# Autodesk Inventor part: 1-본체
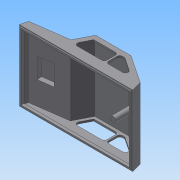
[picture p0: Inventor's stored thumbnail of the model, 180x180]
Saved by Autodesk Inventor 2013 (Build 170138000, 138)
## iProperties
Created: 2015-06
Part Number: 1-본체
Material: 일반
Document SubType Name: Modeling
Designer: Administrator
Density: 1 g/cm^3
Author: Administrator
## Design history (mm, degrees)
sketch "스케치1"
  geometry: L1 (0, 0)-(-122, 0); L2 (-122, 0)-(-119.856, 8); L3 (-119.856, 8)-(-80, 13.463); L4 (-80, 13.463)-(-70.99, 31); L5 (-70.99, 31)-(-32.947, 31); L6 (-32.947, 31)-(-2.947, 11); L7 (-2.947, 11)-(0, 0)
  constraints: 14 end point, 1 horizontal, 1 parallel
  dimensions: "d0" = 122 distance of L1.start L1.end; "d1" = 8 vertical distance of L1.end L2.end; "d2" = 42 horizontal distance of L3.end L1.end; "d6" = 105 deg angle of L1 L2; "d7" = 125 deg angle of L4 L3; "d8" = 20 vertical distance of L6.end L5.end; "d9" = 105 deg angle of L1 L7; "d10" = 31 vertical distance of L5.end L1.start; "d11" = 30 horizontal distance of L5.end L6.end; "d12" = 42.1946 deg angle of L4 L7
extrude "돌출1" new body sketch "스케치1" stored distance "d13" = 76; taper "d14" = 0 deg
sketch "스케치2"
  geometry: L1 (122, -76)-(122, 0) reference; L2 (0, 0)-(122, 0) reference; L3 (0, 0)-(0, -76) reference; L4 (122, -76)-(0, -76) reference; L5 (121, -1)-(121, -75); L6 (121, -75)-(1, -75); L7 (1, -75)-(1, -1); L8 (1, -1)-(121, -1); 1 further point
  constraints: 8 end point, 3 other
  dimensions: "d15" = 1 distance between parallel lines of L8 L2
extrude "돌출2" join sketch "스케치2" distance "d16" = 1; taper "d17" = 0 deg
sketch "스케치3"
  geometry: L1 (0, 0)-(0, 76) reference; L2 (7.79, 51)-(27.79, 51); L3 (27.79, 51)-(27.79, 25); L4 (27.79, 25)-(7.79, 25); L5 (7.79, 25)-(7.79, 51); L6 (-3.21, 0)-(-3.21, 76) reference; 3 further points
  constraints: 8 end point, 2 midpoint, 2 parallel, 1 horizontal, 1 horizontal alignment, 1 perpendicular
  dimensions: "d18" = 20 distance of L2.start L2.end; "d20" = 26 distance of L4.end L2.start; "d21" = 11 distance between parallel lines of L5 L6
extrude "돌출3" join sketch "스케치3" distance "d22" = 5; taper "d23" = 0 deg
feature "쉘1" dims "d55" = 2
sketch "스케치4"
  geometry: L1 (-32.947, 31)-(-70.99, 31) reference; L2 (-70.99, 31)-(-80, 13.463) reference; L3 (-67.937, 26)-(-73.398, 15.371); L4 (-67.937, 26)-(-44.644, 26); L5 (-41.644, 23)-(-41.644, 14); L6 (-44.644, 11)-(-70.73, 11); A1 r 3 centre (-70.73, 14) between (-73.398, 15.371) and (-70.73, 11); A2 r 3 centre (-44.644, 23) between (-41.644, 23) and (-44.644, 26); A3 r 3 centre (-44.644, 14) between (-44.644, 11) and (-41.644, 14); 3 further points
  constraints: 8 end point, 6 point on circle, 6 point on line, 6 tangent, 3 centre point, 3 parallel, 2 equal radius, 1 perpendicular
  dimensions: "d24" = 15 vertical distance of point (-75.644, 11) L3.start; "d26" = 5 distance between parallel lines of L4 L1; "d27" = 5 distance between parallel lines of L3 L2; "d28" = 34 distance of point (-41.644, 11) point (-75.644, 11); "d41" = 3 radius of A1
extrude "돌출4" cut sketch "스케치4" stored distance "d29" = 5; taper "d30" = 0 deg
sketch "스케치5"
  geometry: L1 (-2.947, 11)-(-32.947, 31) reference; L2 (-32.947, 31)-(-70.99, 31) reference; L3 (-36.961, 11)-(-21.87, 11); L4 (-39.961, 14)-(-39.961, 23); L5 (-36.961, 26)-(-35.37, 26); L6 (-33.706, 25.496)-(-20.206, 16.496); A1 r 3 centre (-21.87, 14) between (-21.87, 11) and (-20.206, 16.496); A2 r 3 centre (-36.961, 14) between (-39.961, 14) and (-36.961, 11); A3 r 3 centre (-36.961, 23) between (-36.961, 26) and (-39.961, 23); A4 r 3 centre (-35.37, 23) between (-33.706, 25.496) and (-35.37, 26); 6 further points
  constraints: 8 end point, 8 point on circle, 8 tangent, 6 point on line, 4 centre point, 3 equal radius, 2 perpendicular, 1 parallel
  dimensions: "d46" = 28 distance of point (-39.961, 11) point (-11.961, 11); "d49" = 15 distance of point (-39.961, 11) point (-39.961, 26); "d50" = 5 distance between parallel lines of L5 L2; "d51" = 5 distance between parallel lines of L1 L6; "d52" = 3 radius of A1
extrude "돌출5" cut sketch "스케치5" stored distance "d53" = 5; taper "d54" = 0 deg
node "작업 평면1"
sketch "스케치13"
  geometry: L1 (122, -76)-(122, 0) reference; C1 r 3 at (101, -38); 2 further points
  constraints: 1 centre point, 1 horizontal alignment, 1 midpoint
  dimensions: "d87" = 6 diameter of C1; "d89" = 21 distance from line of L1 C1.centre
extrude "돌출10" join sketch "스케치13" stored distance "d90" = 2; taper "d91" = 0 deg
node "작업 평면3"
node "솔리드1"
other parameters: "d68" = -2
